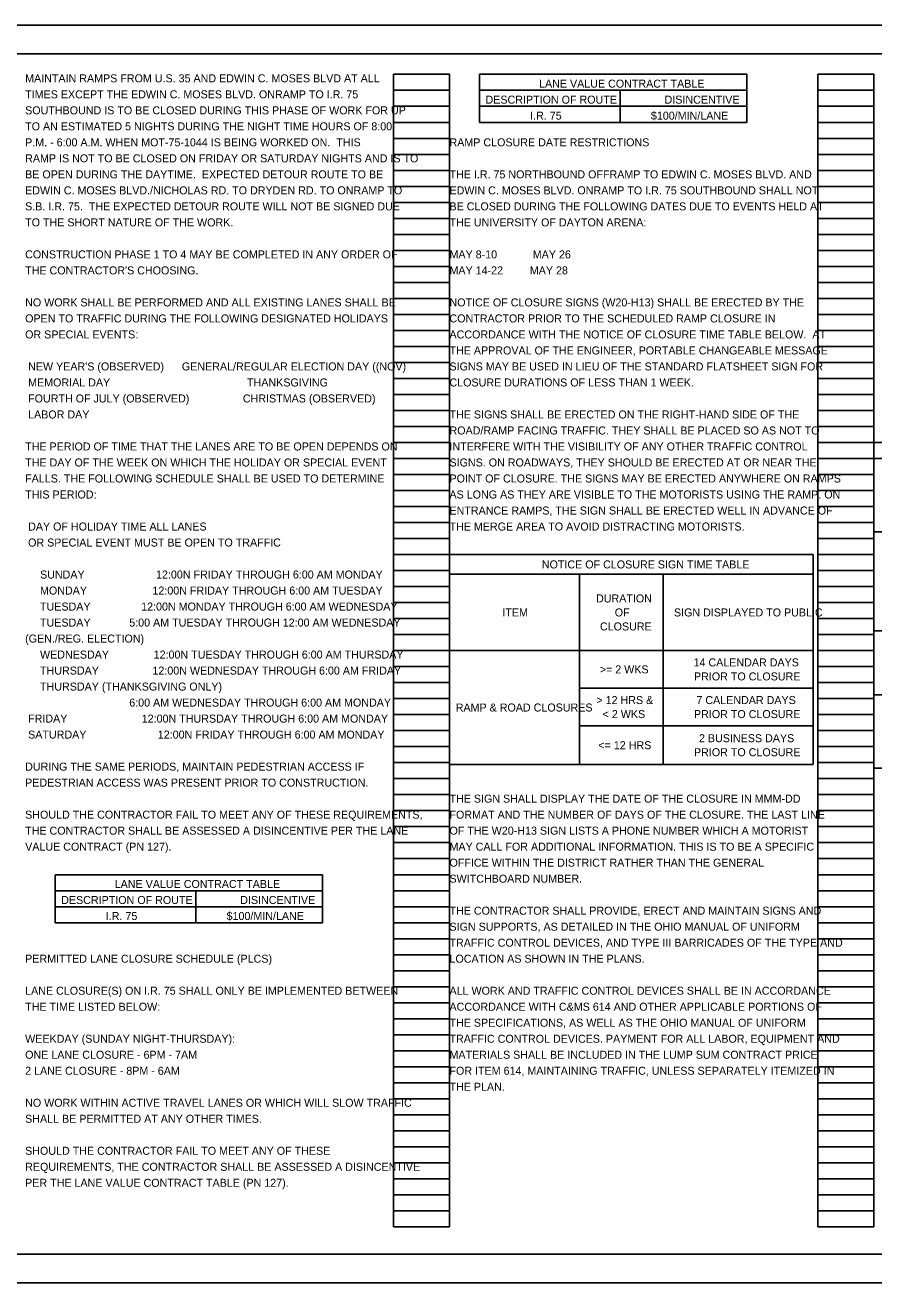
# Model space of a CAD drawing. Extents: x -25.5 to 52.6, y -2.3 to 22.
# Drawn here: x 9.82 to 24.66, y 0 to 22 of the extents above; entities that cross this region are included whole.
import ezdxf

# ---------------------------------------------------------------- set-up
doc = ezdxf.new("R2010")
doc.units = 0
for name, color, linetype in [('SC_Scratch1', 7, 'Continuous'), ('SH_Border', 7, 'Continuous'), ('SH_Cut_Line', 7, 'Continuous'), ('SH_Data', 7, 'Continuous'), ('SH_Text', 7, 'Continuous')]:
    doc.layers.add(name, color=color, linetype=linetype)

msp = doc.modelspace()

# ---------------------------------------------------------------- linework, layer by layer
at = {"layer": 'SC_Scratch1'}
for p, q in [((16.26, 0.98), (16.26, 21.14)), ((16.26, 21.14), (17.24, 21.14)), ((17.24, 0.98), (17.24, 21.14)), ((23.68, 0.98), (23.68, 21.14)), ((23.68, 21.14), (24.66, 21.14)), ((24.66, 0.98), (24.66, 21.14)), ((16.26, 20.86), (17.24, 20.86)), ((23.68, 20.86), (24.66, 20.86)), ((16.26, 20.58), (17.24, 20.58)), ((23.68, 20.58), (24.66, 20.58)), ((16.26, 20.3), (17.24, 20.3)), ((23.68, 20.3), (24.66, 20.3)), ((16.26, 20.02), (17.24, 20.02)), ((23.68, 20.02), (24.66, 20.02)), ((16.26, 19.74), (17.24, 19.74)), ((23.68, 19.74), (24.66, 19.74)), ((16.26, 19.46), (17.24, 19.46)), ((23.68, 19.46), (24.66, 19.46)), ((16.26, 19.18), (17.24, 19.18)), ((23.68, 19.18), (24.66, 19.18)), ((16.26, 18.9), (17.24, 18.9)), ((23.68, 18.9), (24.66, 18.9)), ((16.26, 18.62), (17.24, 18.62)), ((23.68, 18.62), (24.66, 18.62)), ((16.26, 18.34), (17.24, 18.34)), ((23.68, 18.34), (24.66, 18.34)), ((16.26, 18.06), (17.24, 18.06)), ((23.68, 18.06), (24.66, 18.06)), ((16.26, 17.78), (17.24, 17.78)), ((23.68, 17.78), (24.66, 17.78)), ((16.26, 17.5), (17.24, 17.5)), ((23.68, 17.5), (24.66, 17.5)), ((16.26, 17.22), (17.24, 17.22)), ((23.68, 17.22), (24.66, 17.22)), ((16.26, 16.94), (17.24, 16.94)), ((23.68, 16.94), (24.66, 16.94)), ((16.26, 16.66), (17.24, 16.66)), ((23.68, 16.66), (24.66, 16.66)), ((16.26, 16.38), (17.24, 16.38)), ((23.68, 16.38), (24.66, 16.38)), ((16.26, 16.1), (17.24, 16.1)), ((23.68, 16.1), (24.66, 16.1)), ((16.26, 15.82), (17.24, 15.82)), ((23.68, 15.82), (24.66, 15.82)), ((16.26, 15.54), (17.24, 15.54)), ((23.68, 15.54), (24.66, 15.54)), ((16.26, 15.26), (17.24, 15.26)), ((23.68, 15.26), (24.66, 15.26)), ((16.26, 14.98), (17.24, 14.98)), ((23.68, 14.98), (24.66, 14.98)), ((16.26, 14.7), (17.24, 14.7)), ((23.68, 14.7), (24.66, 14.7)), ((16.26, 14.42), (17.24, 14.42)), ((23.68, 14.42), (24.66, 14.42)), ((16.26, 14.14), (17.24, 14.14)), ((23.68, 14.14), (24.66, 14.14)), ((16.26, 13.86), (17.24, 13.86)), ((23.68, 13.86), (24.66, 13.86)), ((16.26, 13.58), (17.24, 13.58)), ((23.68, 13.58), (24.66, 13.58)), ((16.26, 13.3), (17.24, 13.3)), ((23.68, 13.3), (24.66, 13.3)), ((16.26, 13.02), (17.24, 13.02)), ((23.68, 13.02), (24.66, 13.02)), ((16.26, 12.74), (17.24, 12.74)), ((23.68, 12.74), (24.66, 12.74)), ((16.26, 12.46), (17.24, 12.46)), ((23.68, 12.46), (24.66, 12.46)), ((16.26, 12.18), (17.24, 12.18)), ((23.68, 12.18), (24.66, 12.18)), ((16.26, 11.9), (17.24, 11.9)), ((23.68, 11.9), (24.66, 11.9)), ((16.26, 11.62), (17.24, 11.62)), ((23.68, 11.62), (24.66, 11.62)), ((16.26, 11.34), (17.24, 11.34)), ((23.68, 11.34), (24.66, 11.34)), ((16.26, 11.06), (17.24, 11.06)), ((23.68, 11.06), (24.66, 11.06)), ((16.26, 10.78), (17.24, 10.78)), ((23.68, 10.78), (24.66, 10.78)), ((16.26, 10.5), (17.24, 10.5)), ((23.68, 10.5), (24.66, 10.5)), ((16.26, 10.22), (17.24, 10.22)), ((23.68, 10.22), (24.66, 10.22)), ((16.26, 9.94), (17.24, 9.94)), ((23.68, 9.94), (24.66, 9.94)), ((16.26, 9.66), (17.24, 9.66)), ((23.68, 9.66), (24.66, 9.66)), ((16.26, 9.38), (17.24, 9.38)), ((23.68, 9.38), (24.66, 9.38)), ((16.26, 9.1), (17.24, 9.1)), ((23.68, 9.1), (24.66, 9.1)), ((16.26, 8.82), (17.24, 8.82)), ((23.68, 8.82), (24.66, 8.82)), ((16.26, 8.54), (17.24, 8.54)), ((23.68, 8.54), (24.66, 8.54)), ((16.26, 8.26), (17.24, 8.26)), ((23.68, 8.26), (24.66, 8.26)), ((16.26, 7.98), (17.24, 7.98)), ((23.68, 7.98), (24.66, 7.98)), ((16.26, 7.7), (17.24, 7.7)), ((23.68, 7.7), (24.66, 7.7)), ((16.26, 7.42), (17.24, 7.42)), ((23.68, 7.42), (24.66, 7.42)), ((16.26, 7.14), (17.24, 7.14)), ((23.68, 7.14), (24.66, 7.14)), ((16.26, 6.86), (17.24, 6.86)), ((23.68, 6.86), (24.66, 6.86)), ((16.26, 6.58), (17.24, 6.58)), ((23.68, 6.58), (24.66, 6.58)), ((16.26, 6.3), (17.24, 6.3)), ((23.68, 6.3), (24.66, 6.3)), ((16.26, 6.02), (17.24, 6.02)), ((23.68, 6.02), (24.66, 6.02)), ((16.26, 5.74), (17.24, 5.74)), ((23.68, 5.74), (24.66, 5.74)), ((16.26, 5.46), (17.24, 5.46)), ((23.68, 5.46), (24.66, 5.46)), ((16.26, 5.18), (17.24, 5.18)), ((23.68, 5.18), (24.66, 5.18)), ((16.26, 4.9), (17.24, 4.9)), ((23.68, 4.9), (24.66, 4.9)), ((16.26, 4.62), (17.24, 4.62)), ((23.68, 4.62), (24.66, 4.62)), ((16.26, 4.34), (17.24, 4.34)), ((23.68, 4.34), (24.66, 4.34)), ((16.26, 4.06), (17.24, 4.06)), ((23.68, 4.06), (24.66, 4.06)), ((16.26, 3.78), (17.24, 3.78)), ((23.68, 3.78), (24.66, 3.78)), ((16.26, 3.5), (17.24, 3.5)), ((23.68, 3.5), (24.66, 3.5)), ((16.26, 3.22), (17.24, 3.22)), ((23.68, 3.22), (24.66, 3.22)), ((16.26, 2.94), (17.24, 2.94)), ((23.68, 2.94), (24.66, 2.94)), ((16.26, 2.66), (17.24, 2.66)), ((23.68, 2.66), (24.66, 2.66)), ((16.26, 2.38), (17.24, 2.38)), ((23.68, 2.38), (24.66, 2.38)), ((16.26, 2.1), (17.24, 2.1)), ((23.68, 2.1), (24.66, 2.1)), ((16.26, 1.82), (17.24, 1.82)), ((23.68, 1.82), (24.66, 1.82)), ((16.26, 1.54), (17.24, 1.54)), ((23.68, 1.54), (24.66, 1.54)), ((16.26, 1.26), (17.24, 1.26)), ((23.68, 1.26), (24.66, 1.26)), ((16.26, 0.98), (17.24, 0.98)), ((23.68, 0.98), (24.66, 0.98))]:
    msp.add_line(p, q, dxfattribs=at)
at = {"layer": 'SH_Border'}
msp.add_lwpolyline([(1.5, 21.5), (33.5, 21.5), (33.5, 0.5), (1.5, 0.5)], close=True, dxfattribs=at)
at = {"layer": 'SH_Cut_Line'}
msp.add_lwpolyline([(0, 0), (34, 0), (34, 22), (0, 22)], close=True, dxfattribs=at)
at = {"layer": 'SH_Data'}
for p, q in [((24.66, 14.7), (31.133, 14.7)), ((24.66, 14.7), (24.66, 9.001)), ((24.66, 14.42), (31.133, 14.42)), ((24.66, 13.135), (31.133, 13.135)), ((17.24, 12.74), (23.598, 12.74)), ((17.24, 12.74), (17.24, 9.067)), ((23.598, 12.74), (23.598, 9.067)), ((17.24, 12.394), (23.598, 12.394)), ((19.513, 12.394), (19.513, 9.067)), ((20.979, 12.394), (20.979, 9.067)), ((24.66, 11.406), (31.133, 11.406)), ((17.24, 11.06), (23.598, 11.06)), ((19.513, 10.401), (23.598, 10.401)), ((24.66, 10.286), (31.133, 10.286)), ((19.513, 9.742), (23.598, 9.742)), ((17.24, 9.067), (23.598, 9.067)), ((24.66, 9.001), (31.133, 9.001))]:
    msp.add_line(p, q, dxfattribs=at)
at = {"layer": 'SH_Text'}
for p, q in [((17.766, 21.14), (22.437, 21.14)), ((17.766, 20.3), (17.766, 21.14)), ((22.437, 20.3), (22.437, 21.14)), ((17.766, 20.86), (22.437, 20.86)), ((20.224, 20.3), (20.224, 20.86)), ((17.766, 20.58), (22.437, 20.58)), ((17.766, 20.3), (22.437, 20.3)), ((10.346, 7.14), (15.017, 7.14)), ((10.346, 6.3), (10.346, 7.14)), ((15.017, 6.3), (15.017, 7.14)), ((10.346, 6.86), (15.017, 6.86)), ((12.804, 6.3), (12.804, 6.86)), ((10.346, 6.58), (15.017, 6.58)), ((10.346, 6.3), (15.017, 6.3))]:
    msp.add_line(p, q, dxfattribs=at)

# ---------------------------------------------------------------- texts
for s, p in [('MAINTAIN RAMPS FROM U.S. 35 AND EDWIN C. MOSES BLVD AT ALL ', (9.82, 21)), ('                    LANE VALUE CONTRACT TABLE', (17.766, 20.907)), ('TIMES EXCEPT THE EDWIN C. MOSES BLVD. ONRAMP TO I.R. 75 ', (9.82, 20.72)), ('  DESCRIPTION OF ROUTE                DISINCENTIVE', (17.766, 20.627)), ('SOUTHBOUND IS TO BE CLOSED DURING THIS PHASE OF WORK FOR UP ', (9.82, 20.44)), ('                 I.R. 75                              $100/MIN/LANE', (17.766, 20.347)), ('TO AN ESTIMATED 5 NIGHTS DURING THE NIGHT TIME HOURS OF 8:00 ', (9.82, 20.16)), ('P.M. - 6:00 A.M. WHEN MOT-75-1044 IS BEING WORKED ON.  THIS ', (9.82, 19.88)), ('RAMP CLOSURE DATE RESTRICTIONS', (17.24, 19.88)), ('RAMP IS NOT TO BE CLOSED ON FRIDAY OR SATURDAY NIGHTS AND IS TO ', (9.82, 19.6)), ('BE OPEN DURING THE DAYTIME.  EXPECTED DETOUR ROUTE TO BE ', (9.82, 19.32)), ('THE I.R. 75 NORTHBOUND OFFRAMP TO EDWIN C. MOSES BLVD. AND ', (17.24, 19.32)), ('EDWIN C. MOSES BLVD./NICHOLAS RD. TO DRYDEN RD. TO ONRAMP TO ', (9.82, 19.04)), ('EDWIN C. MOSES BLVD. ONRAMP TO I.R. 75 SOUTHBOUND SHALL NOT ', (17.24, 19.04)), ('S.B. I.R. 75.  THE EXPECTED DETOUR ROUTE WILL NOT BE SIGNED DUE ', (9.82, 18.76)), ('BE CLOSED DURING THE FOLLOWING DATES DUE TO EVENTS HELD AT ', (17.24, 18.76)), ('TO THE SHORT NATURE OF THE WORK.', (9.82, 18.48)), ('THE UNIVERSITY OF DAYTON ARENA:', (17.24, 18.48)), ('CONSTRUCTION PHASE 1 TO 4 MAY BE COMPLETED IN ANY ORDER OF ', (9.82, 17.92)), ('MAY 8-10            MAY 26', (17.24, 17.92)), ("THE CONTRACTOR'S CHOOSING.", (9.82, 17.64)), ('MAY 14-22         MAY 28', (17.24, 17.64)), ('NO WORK SHALL BE PERFORMED AND ALL EXISTING LANES SHALL BE', (9.82, 17.08)), ('NOTICE OF CLOSURE SIGNS (W20-H13) SHALL BE ERECTED BY THE ', (17.24, 17.08)), ('OPEN TO TRAFFIC DURING THE FOLLOWING DESIGNATED HOLIDAYS', (9.82, 16.8)), ('CONTRACTOR PRIOR TO THE SCHEDULED RAMP CLOSURE IN ', (17.24, 16.8)), ('OR SPECIAL EVENTS:', (9.82, 16.52)), ('ACCORDANCE WITH THE NOTICE OF CLOSURE TIME TABLE BELOW.  AT ', (17.24, 16.52)), ('THE APPROVAL OF THE ENGINEER, PORTABLE CHANGEABLE MESSAGE ', (17.24, 16.24)), (" NEW YEAR'S (OBSERVED)      GENERAL/REGULAR ELECTION DAY ((NOV)", (9.82, 15.96)), ('SIGNS MAY BE USED IN LIEU OF THE STANDARD FLATSHEET SIGN FOR ', (17.24, 15.96)), (' MEMORIAL DAY                                              THANKSGIVING', (9.82, 15.68)), ('CLOSURE DURATIONS OF LESS THAN 1 WEEK.', (17.24, 15.68)), (' FOURTH OF JULY (OBSERVED)                  CHRISTMAS (OBSERVED)', (9.82, 15.4)), (' LABOR DAY', (9.82, 15.12)), ('THE SIGNS SHALL BE ERECTED ON THE RIGHT-HAND SIDE OF THE ', (17.24, 15.12)), ('ROAD/RAMP FACING TRAFFIC. THEY SHALL BE PLACED SO AS NOT TO ', (17.24, 14.84)), ('THE PERIOD OF TIME THAT THE LANES ARE TO BE OPEN DEPENDS ON', (9.82, 14.56)), ('INTERFERE WITH THE VISIBILITY OF ANY OTHER TRAFFIC CONTROL ', (17.24, 14.56)), ('THE DAY OF THE WEEK ON WHICH THE HOLIDAY OR SPECIAL EVENT', (9.82, 14.28)), ('SIGNS. ON ROADWAYS, THEY SHOULD BE ERECTED AT OR NEAR THE ', (17.24, 14.28)), ('FALLS. THE FOLLOWING SCHEDULE SHALL BE USED TO DETERMINE', (9.82, 14)), ('POINT OF CLOSURE. THE SIGNS MAY BE ERECTED ANYWHERE ON RAMPS ', (17.24, 14)), ('THIS PERIOD:', (9.82, 13.72)), ('AS LONG AS THEY ARE VISIBLE TO THE MOTORISTS USING THE RAMP. ON ', (17.24, 13.72)), ('ENTRANCE RAMPS, THE SIGN SHALL BE ERECTED WELL IN ADVANCE OF ', (17.24, 13.44)), (' DAY OF HOLIDAY TIME ALL LANES', (9.82, 13.16)), ('THE MERGE AREA TO AVOID DISTRACTING MOTORISTS.', (17.24, 13.16)), (' OR SPECIAL EVENT MUST BE OPEN TO TRAFFIC', (9.82, 12.88)), ('NOTICE OF CLOSURE SIGN TIME TABLE', (18.855, 12.497)), ('     SUNDAY                        12:00N FRIDAY THROUGH 6:00 AM MONDAY', (9.82, 12.32)), ('     MONDAY                      12:00N FRIDAY THROUGH 6:00 AM TUESDAY', (9.82, 12.04)), ('     TUESDAY                 12:00N MONDAY THROUGH 6:00 AM WEDNESDAY', (9.82, 11.76)), ('DURATION ', (19.802, 11.902)), ('ITEM', (18.165, 11.657)), ('OF ', (20.13, 11.657)), ('SIGN DISPLAYED TO PUBLIC', (21.165, 11.657)), ('     TUESDAY             5:00 AM TUESDAY THROUGH 12:00 AM WEDNESDAY', (9.82, 11.48)), ('CLOSURE', (19.871, 11.412)), ('(GEN./REG. ELECTION)      ', (9.82, 11.2)), ('     WEDNESDAY               12:00N TUESDAY THROUGH 6:00 AM THURSDAY', (9.82, 10.92)), ('     THURSDAY                  12:00N WEDNESDAY THROUGH 6:00 AM FRIDAY', (9.82, 10.64)), ('>= 2 WKS', (19.868, 10.661)), ('14 CALENDAR DAYS ', (21.508, 10.783)), ('PRIOR TO CLOSURE', (21.515, 10.538)), ('     THURSDAY (THANKSGIVING ONLY)', (9.82, 10.36)), ('                                   6:00 AM WEDNESDAY THROUGH 6:00 AM MONDAY', (9.82, 10.08)), ('RAMP & ROAD CLOSURES', (17.349, 9.994)), ('> 12 HRS & ', (19.809, 10.124)), ('7 CALENDAR DAYS ', (21.558, 10.124)), (' FRIDAY                         12:00N THURSDAY THROUGH 6:00 AM MONDAY', (9.82, 9.8)), ('< 2 WKS', (19.918, 9.879)), ('PRIOR TO CLOSURE', (21.515, 9.879)), (' SATURDAY                        12:00N FRIDAY THROUGH 6:00 AM MONDAY', (9.82, 9.52)), ('<= 12 HRS', (19.843, 9.335)), ('2 BUSINESS DAYS ', (21.603, 9.457)), ('PRIOR TO CLOSURE', (21.515, 9.212)), ('DURING THE SAME PERIODS, MAINTAIN PEDESTRIAN ACCESS IF', (9.82, 8.96)), ('PEDESTRIAN ACCESS WAS PRESENT PRIOR TO CONSTRUCTION.', (9.82, 8.68)), ('THE SIGN SHALL DISPLAY THE DATE OF THE CLOSURE IN MMM-DD ', (17.24, 8.4)), ('SHOULD THE CONTRACTOR FAIL TO MEET ANY OF THESE REQUIREMENTS,', (9.82, 8.12)), ('FORMAT AND THE NUMBER OF DAYS OF THE CLOSURE. THE LAST LINE ', (17.24, 8.12)), ('THE CONTRACTOR SHALL BE ASSESSED A DISINCENTIVE PER THE LANE', (9.82, 7.84)), ('OF THE W20-H13 SIGN LISTS A PHONE NUMBER WHICH A MOTORIST ', (17.24, 7.84)), ('VALUE CONTRACT (PN 127).', (9.82, 7.56)), ('MAY CALL FOR ADDITIONAL INFORMATION. THIS IS TO BE A SPECIFIC ', (17.24, 7.56)), ('OFFICE WITHIN THE DISTRICT RATHER THAN THE GENERAL ', (17.24, 7.28)), ('                    LANE VALUE CONTRACT TABLE', (10.346, 6.907)), ('SWITCHBOARD NUMBER.', (17.24, 7)), ('  DESCRIPTION OF ROUTE                DISINCENTIVE', (10.346, 6.627)), ('                 I.R. 75                              $100/MIN/LANE', (10.346, 6.347)), ('THE CONTRACTOR SHALL PROVIDE, ERECT AND MAINTAIN SIGNS AND', (17.24, 6.44)), ('SIGN SUPPORTS, AS DETAILED IN THE OHIO MANUAL OF UNIFORM', (17.24, 6.16)), ('TRAFFIC CONTROL DEVICES, AND TYPE III BARRICADES OF THE TYPE AND', (17.24, 5.88)), ('PERMITTED LANE CLOSURE SCHEDULE (PLCS)', (9.82, 5.6)), ('LOCATION AS SHOWN IN THE PLANS.', (17.24, 5.6)), ('LANE CLOSURE(S) ON I.R. 75 SHALL ONLY BE IMPLEMENTED BETWEEN ', (9.82, 5.04)), ('ALL WORK AND TRAFFIC CONTROL DEVICES SHALL BE IN ACCORDANCE', (17.24, 5.04)), ('THE TIME LISTED BELOW:', (9.82, 4.76)), ('ACCORDANCE WITH C&MS 614 AND OTHER APPLICABLE PORTIONS OF ', (17.24, 4.76)), ('THE SPECIFICATIONS, AS WELL AS THE OHIO MANUAL OF UNIFORM', (17.24, 4.48)), ('WEEKDAY (SUNDAY NIGHT-THURSDAY):', (9.82, 4.2)), ('TRAFFIC CONTROL DEVICES. PAYMENT FOR ALL LABOR, EQUIPMENT AND', (17.24, 4.2)), ('ONE LANE CLOSURE - 6PM - 7AM', (9.82, 3.92)), ('MATERIALS SHALL BE INCLUDED IN THE LUMP SUM CONTRACT PRICE', (17.24, 3.92)), ('2 LANE CLOSURE - 8PM - 6AM', (9.82, 3.64)), ('FOR ITEM 614, MAINTAINING TRAFFIC, UNLESS SEPARATELY ITEMIZED IN', (17.24, 3.64)), ('THE PLAN.', (17.24, 3.36)), ('NO WORK WITHIN ACTIVE TRAVEL LANES OR WHICH WILL SLOW TRAFFIC ', (9.82, 3.08)), ('SHALL BE PERMITTED AT ANY OTHER TIMES.', (9.82, 2.8)), ('SHOULD THE CONTRACTOR FAIL TO MEET ANY OF THESE ', (9.82, 2.24)), ('REQUIREMENTS, THE CONTRACTOR SHALL BE ASSESSED A DISINCENTIVE ', (9.82, 1.96)), ('PER THE LANE VALUE CONTRACT TABLE (PN 127).', (9.82, 1.68))]:
    msp.add_text(s, height=0.14, dxfattribs=at).set_placement(p)

doc.saveas('drawing.dxf')
